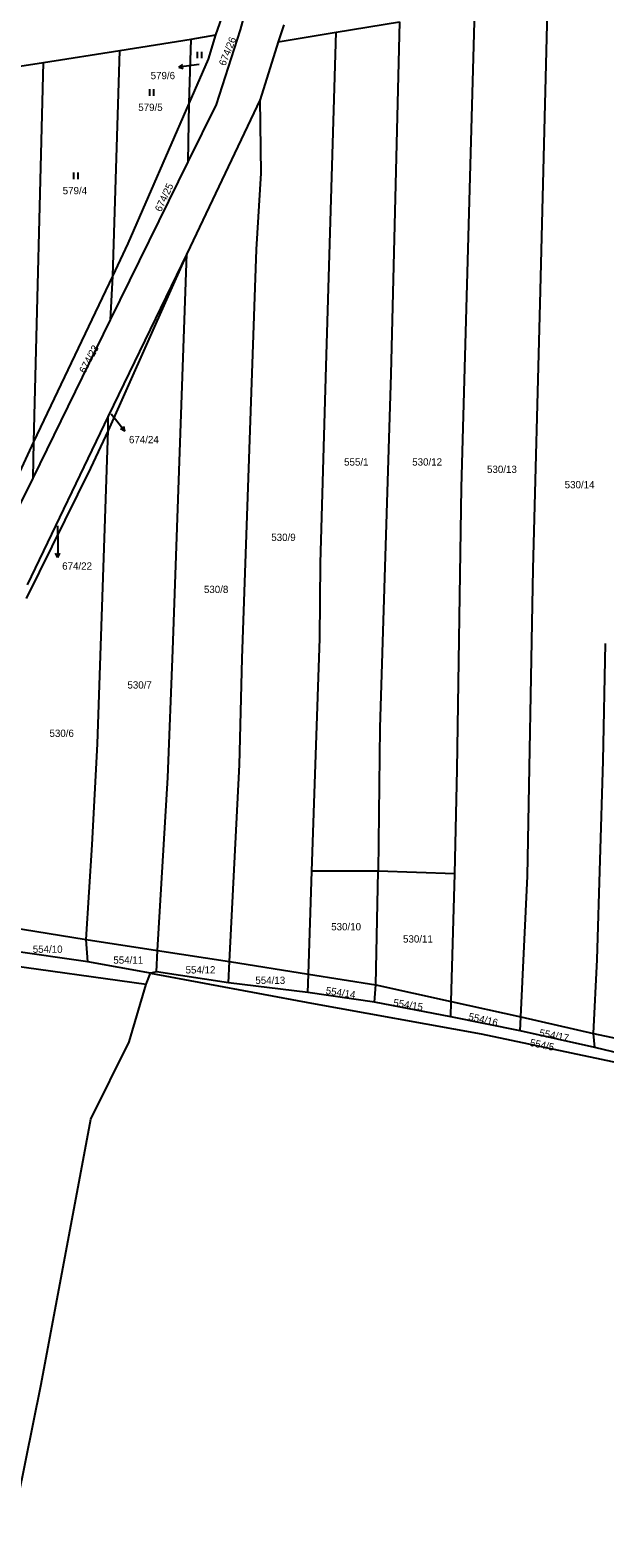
# Model space of a CAD drawing. Extents: x -7483133 to -743907, y -11317770 to -1129777.
# Drawn here: x -746957.4 to -746823.4, y -1133086.4 to -1132734.9 of the extents above; entities that cross this region are included whole.
import ezdxf

# ---------------------------------------------------------------- set-up
doc = ezdxf.new("R2010")
doc.units = 0
for name, color, linetype in [('Hranice parcel', 7, 'Continuous'), ('Parcelní čísla', 7, 'Continuous'), ('Pop  PČ popisy', 7, 'Continuous'), ('Značky kultur', 7, 'Continuous')]:
    doc.layers.add(name, color=color, linetype=linetype)

msp = doc.modelspace()

# ---------------------------------------------------------------- linework, layer by layer
at = {"layer": 'Hranice parcel'}
for p, q in [((-746914.12, -1132735.95), (-746909.2, -1132721.89)), ((-746919.89, -1132737.02), (-746914.12, -1132735.95)), ((-746898.28, -1132733.66), (-746899.56, -1132737.65)), ((-746899.56, -1132737.65), (-746886.05, -1132735.37)), ((-746886.05, -1132735.37), (-746871.34, -1132732.99)), ((-746936.5, -1132739.63), (-746919.89, -1132737.02)), ((-746920.36, -1132752.02), (-746919.89, -1132737.02)), ((-746899.56, -1132737.65), (-746903.77, -1132751.06)), ((-746970.6, -1132744.98), (-746954.26, -1132742.42)), ((-746956.52, -1132830.88), (-746954.26, -1132742.42)), ((-746954.26, -1132742.42), (-746936.5, -1132739.63)), ((-746938.16, -1132792.24), (-746936.5, -1132739.63)), ((-746903.77, -1132751.06), (-746920.9, -1132787.04)), ((-746920.54, -1132765.57), (-746920.36, -1132752.02)), ((-746938.66, -1132802.47), (-746920.54, -1132765.57)), ((-746920.9, -1132787.04), (-746939.25, -1132824.92)), ((-746920.9, -1132787.04), (-746939.21, -1132828.21)), ((-746956.52, -1132830.88), (-746938.16, -1132792.24)), ((-746938.66, -1132802.47), (-746938.16, -1132792.24)), ((-746956.71, -1132839.31), (-746938.66, -1132802.47)), ((-746939.25, -1132824.92), (-746958.1, -1132864.23)), ((-746939.21, -1132828.21), (-746939.25, -1132824.92)), ((-746975.22, -1132871.09), (-746956.52, -1132830.88)), ((-746956.71, -1132839.31), (-746956.52, -1132830.88)), ((-746975.46, -1132876.91), (-746956.71, -1132839.31)), ((-746892.56, -1132954.98), (-746891.72, -1132930.99)), ((-746876.3, -1132930.99), (-746891.72, -1132930.99)), ((-746876.83, -1132957.48), (-746876.3, -1132930.99)), ((-746858.43, -1132931.63), (-746876.3, -1132930.99)), ((-746859.24, -1132961.35), (-746858.43, -1132931.63)), ((-746962.08, -1132944.03), (-746944.33, -1132946.92)), ((-746943.99, -1132952.09), (-746962.38, -1132949.49)), ((-746943.99, -1132952.09), (-746944.33, -1132946.92)), ((-746944.33, -1132946.92), (-746927.76, -1132949.47)), ((-746927.99, -1132954.47), (-746927.76, -1132949.47)), ((-746927.76, -1132949.47), (-746910.94, -1132952.06)), ((-746929.35, -1132954.76), (-746943.99, -1132952.09)), ((-746911.16, -1132957.04), (-746910.94, -1132952.06)), ((-746910.94, -1132952.06), (-746892.56, -1132954.98)), ((-746930.34, -1132957.34), (-746929.35, -1132954.76)), ((-746927.99, -1132954.47), (-746929.35, -1132954.76)), ((-746911.16, -1132957.04), (-746927.99, -1132954.47)), ((-746892.71, -1132959.25), (-746911.16, -1132957.04)), ((-746892.71, -1132959.25), (-746892.56, -1132954.98)), ((-746892.56, -1132954.98), (-746876.83, -1132957.48)), ((-746877.16, -1132961.53), (-746892.71, -1132959.25)), ((-746877.16, -1132961.53), (-746876.83, -1132957.48)), ((-746876.83, -1132957.48), (-746859.24, -1132961.35)), ((-746859.32, -1132964.96), (-746877.16, -1132961.53)), ((-746859.32, -1132964.96), (-746859.24, -1132961.35)), ((-746859.24, -1132961.35), (-746843.01, -1132964.9)), ((-746843.15, -1132968.18), (-746859.32, -1132964.96)), ((-746843.15, -1132968.18), (-746843.01, -1132964.9)), ((-746843.01, -1132964.9), (-746826.09, -1132968.83)), ((-746825.76, -1132972.07), (-746843.15, -1132968.18)), ((-746825.76, -1132972.07), (-746826.09, -1132968.83)), ((-746826.09, -1132968.83), (-746783.4, -1132977.73)), ((-746783.4, -1132982.44), (-746825.76, -1132972.07))]:
    msp.add_line(p, q, dxfattribs=at)
for points in [[(-746920.54, -1132765.57), (-746913.98, -1132752.22), (-746908.41, -1132734.81), (-746904.63, -1132721.03)], [(-746843.01, -1132964.9), (-746841.51, -1132932.14), (-746840.15, -1132860.48), (-746838.51, -1132798.6), (-746836.72, -1132727.3)], [(-746858.43, -1132931.63), (-746857.9, -1132907.3), (-746856.9, -1132841.49), (-746853.76, -1132730.15)], [(-746920.36, -1132752.02), (-746915.84, -1132741.64), (-746914.12, -1132735.95)], [(-746891.72, -1132930.99), (-746889.9, -1132876.76), (-746889.71, -1132859.18), (-746888.44, -1132813.22), (-746886.05, -1132735.37)], [(-746871.34, -1132732.99), (-746873.31, -1132815.08), (-746875.88, -1132897.58), (-746876.3, -1132930.99)], [(-746938.16, -1132792.24), (-746934.54, -1132784.62), (-746920.36, -1132752.02)], [(-746910.94, -1132952.06), (-746908.59, -1132906.22), (-746907.95, -1132881.39), (-746904.66, -1132786.03), (-746903.52, -1132768.26), (-746903.77, -1132751.06)], [(-746927.76, -1132949.47), (-746925.29, -1132909.16), (-746924.16, -1132879.46), (-746920.9, -1132787.04)], [(-746939.21, -1132828.21), (-746943.35, -1132836.99), (-746958.34, -1132867.4)], [(-746944.33, -1132946.92), (-746942.99, -1132924.86), (-746941.7, -1132901.31), (-746939.21, -1132828.21)], [(-746826.09, -1132968.83), (-746825.23, -1132951.59), (-746823.81, -1132905.23), (-746823.3, -1132877.9)], [(-746999.22, -1132948.35), (-746965.02, -1132952.48), (-746930.34, -1132957.34)], [(-746962.09, -1133086.41), (-746954.85, -1133050.6), (-746943.29, -1132988.79), (-746934.3, -1132970.8), (-746930.34, -1132957.34)], [(-746929.35, -1132954.76), (-746891.82, -1132961.76), (-746852.29, -1132968.9), (-746817.33, -1132976.32), (-746744.69, -1132994.17), (-746722.86, -1132997.73), (-746660.65, -1133006.44), (-746628.31, -1133009.07)]]:
    msp.add_lwpolyline(points, dxfattribs=at)
at = {"layer": 'Pop  PČ popisy'}
for p, q in [((-746922.77, -1132743.5), (-746921.84, -1132742.88)), ((-746918.02, -1132742.91), (-746919.79, -1132743.13)), ((-746919.79, -1132743.13), (-746922.77, -1132743.5)), ((-746922.77, -1132743.5), (-746921.71, -1132743.87)), ((-746938.53, -1132824.32), (-746937.22, -1132826)), ((-746937.22, -1132826), (-746935.37, -1132828.36)), ((-746935.37, -1132828.36), (-746935.59, -1132827.27)), ((-746935.37, -1132828.36), (-746936.38, -1132827.88)), ((-746951, -1132850.43), (-746950.96, -1132854.85)), ((-746950.96, -1132854.85), (-746950.96, -1132857.85)), ((-746950.96, -1132857.85), (-746951.46, -1132856.85)), ((-746950.96, -1132857.85), (-746950.46, -1132856.85))]:
    msp.add_line(p, q, dxfattribs=at)
at = {"layer": 'Značky kultur'}
for p, q in [((-746918.38, -1132741.45), (-746918.38, -1132739.95)), ((-746917.38, -1132741.45), (-746917.38, -1132739.95)), ((-746929.54, -1132750.19), (-746929.54, -1132748.69)), ((-746928.54, -1132750.19), (-746928.54, -1132748.69)), ((-746947.19, -1132769.6), (-746947.19, -1132768.1)), ((-746946.19, -1132769.6), (-746946.19, -1132768.1))]:
    msp.add_line(p, q, dxfattribs=at)

# ---------------------------------------------------------------- texts
at = {"layer": 'Parcelní čísla'}
for s, rotation, p in [('674/26', 68, (-746911.93, -1132743.36)), ('674/25', 65, (-746926.89, -1132777.39)), ('674/23', 62, (-746944.59, -1132815.05)), ('554/14', 351, (-746888.6, -1132959.59)), ('554/15', 351, (-746872.86, -1132962.42)), ('554/16', 347, (-746855.37, -1132965.62)), ('554/17', 349, (-746838.84, -1132969.43)), ('554/5', 348, (-746841.04, -1132971.7))]:
    msp.add_text(s, height=1.7, rotation=rotation, dxfattribs=at).set_placement(p)
for s, p in [('579/6', (-746929.32, -1132746.33)), ('579/5', (-746932.21, -1132753.74)), ('579/4', (-746949.82, -1132773.15)), ('674/24', (-746934.37, -1132831.2)), ('555/1', (-746884.23, -1132836.42)), ('530/12', (-746868.35, -1132836.42)), ('530/13', (-746850.91, -1132838.13)), ('530/14', (-746832.81, -1132841.71)), ('530/9', (-746901.2, -1132853.99)), ('674/22', (-746949.94, -1132860.68)), ('530/8', (-746916.9, -1132866.13)), ('530/7', (-746934.73, -1132888.4)), ('530/6', (-746952.9, -1132899.67)), ('530/10', (-746887.23, -1132944.77)), ('530/11', (-746870.49, -1132947.62)), ('554/10', (-746956.8, -1132950.01)), ('554/11', (-746938.01, -1132952.55)), ('554/12', (-746921.18, -1132954.83)), ('554/13', (-746904.91, -1132957.26))]:
    msp.add_text(s, height=1.7, dxfattribs=at).set_placement(p)

doc.saveas('drawing.dxf')
